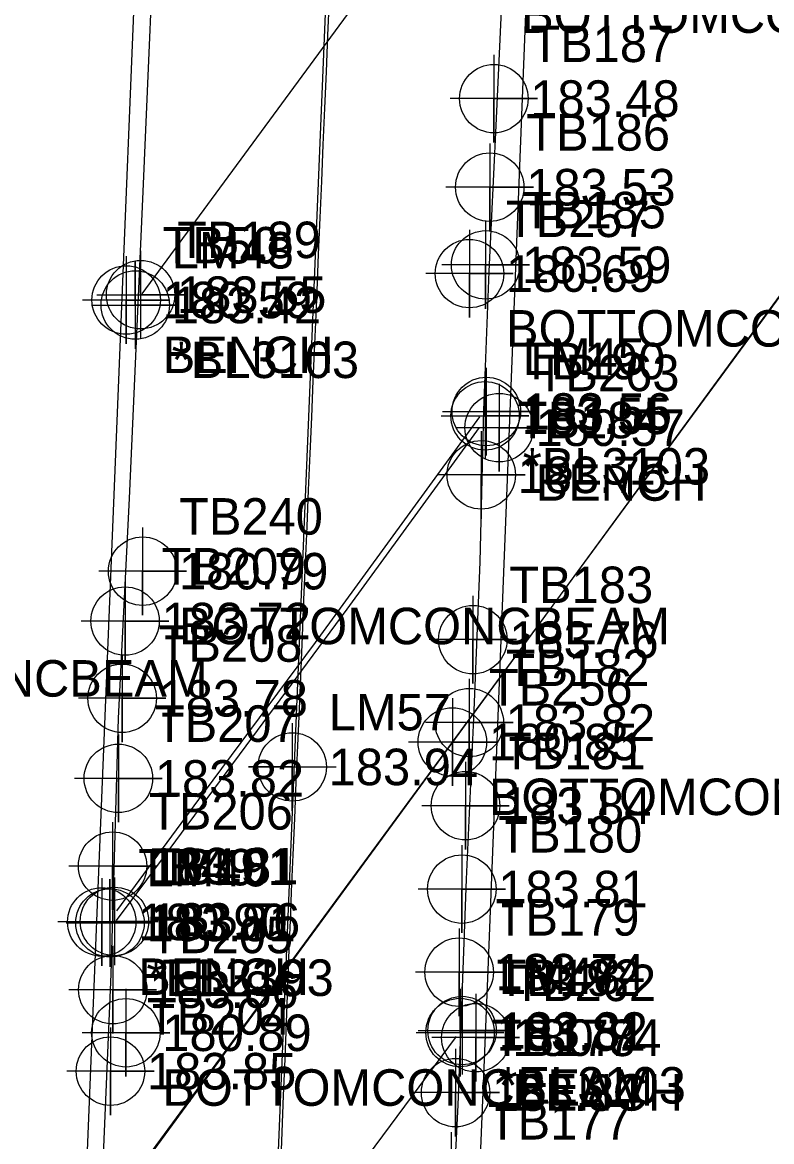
# Model space of a CAD drawing. Extents: x 2262665 to 2270527, y 505476 to 514960.
# Drawn here: x 2266313.3 to 2266364.6, y 510590.2 to 510666.8 of the extents above; entities that cross this region are included whole.
import ezdxf

# ---------------------------------------------------------------- set-up
doc = ezdxf.new("R2010")
doc.units = 0
for name, color, linetype in [('Default Symbol CELL', 7, 'Continuous'), ('Default Symbol Cogo Comment', 7, 'Continuous'), ('Default Symbol Cogo Elevation', 7, 'Continuous'), ('Default Symbol Cogo Number', 7, 'Continuous'), ('Exist Guardrail', 7, 'Continuous'), ('Exist Horizontal Alignment', 7, 'Continuous'), ('Exist Railroads Standard Gauge', 7, 'Continuous'), ('Exist Roads EOT', 7, 'Continuous'), ('Exist Roads EOT Cogo Elevation', 7, 'Continuous'), ('Exist Roads EOT Cogo Number', 7, 'Continuous'), ('Exist Roads EOT Cogo Point CELL', 7, 'Continuous'), ('Exist Structure Major Bridge Seam', 7, 'Continuous'), ('Exist Structure Major Bridge Seam Cogo Comment', 7, 'Continuous'), ('Exist Structure Major Bridge Seam Cogo Elevation', 7, 'Continuous'), ('Exist Structure Major Bridge Seam Cogo Number', 7, 'Continuous'), ('Exist Structure Major Bridge Seam Cogo Point CELL', 7, 'Continuous'), ('Exist Structure Major Deck Tunnel Box Culvert', 7, 'Continuous'), ('Exist Structure Minor Drop Inlet Cogo Elevation', 7, 'Continuous'), ('Exist Structure Minor Drop Inlet Cogo Number', 7, 'Continuous'), ('Exist Structure Minor Drop Inlet Cogo Point CELL', 7, 'Continuous')]:
    doc.layers.add(name, color=color, linetype=linetype)

msp = doc.modelspace()

# ---------------------------------------------------------------- linework, layer by layer
at = {"layer": 'Default Symbol CELL'}
for points in [[(2266343.875, 510652.617), (2266343.875, 510646.617), (2266343.875, 510649.617), (2266346.875, 510649.617), (2266340.875, 510649.617)], [(2266320.361, 510650.809), (2266320.361, 510644.809), (2266320.361, 510647.809), (2266323.361, 510647.809), (2266317.361, 510647.809)], [(2266345.909, 510642.068), (2266345.909, 510636.068), (2266345.909, 510639.068), (2266348.909, 510639.068), (2266342.909, 510639.068)], [(2266321.485, 510632.246), (2266321.485, 510626.246), (2266321.485, 510629.246), (2266324.485, 510629.246), (2266318.485, 510629.246)], [(2266342.701, 510620.552), (2266342.701, 510614.552), (2266342.701, 510617.552), (2266345.701, 510617.552), (2266339.701, 510617.552)], [(2266318.688, 510608.237), (2266318.688, 510602.237), (2266318.688, 510605.237), (2266321.688, 510605.237), (2266315.688, 510605.237)], [(2266320.34, 510600.651), (2266320.34, 510594.651), (2266320.34, 510597.651), (2266323.34, 510597.651), (2266317.34, 510597.651)], [(2266344.308, 510600.318), (2266344.308, 510594.318), (2266344.308, 510597.318), (2266347.308, 510597.318), (2266341.308, 510597.318)]]:
    msp.add_lwpolyline(points, dxfattribs=at)
for centre in [(2266343.875, 510649.617), (2266320.361, 510647.809), (2266345.909, 510639.068), (2266321.485, 510629.246), (2266342.701, 510617.552), (2266318.688, 510605.237), (2266320.34, 510597.651), (2266344.308, 510597.318)]:
    msp.add_circle(centre, 2.344, dxfattribs=at)
at = {"layer": 'Exist Guardrail'}
for points in [[(2266353.106, 510731.751), (2266351.624, 510731.138), (2266350.675, 510729.801), (2266350.418, 510728.723), (2266350.359, 510727.905), (2266350.321, 510727.053), (2266350.321, 510727.053), (2266348.476, 510686.53), (2266345.137, 510601.939), (2266341.529, 510514.133), (2266341.529, 510514.133), (2266342.739, 510511.419)], [(2266310.275, 510472.029), (2266312.516, 510474.848), (2266312.727, 510477.084), (2266316.621, 510562.638), (2266320.054, 510647.377), (2266321.754, 510688.765), (2266321.754, 510688.765), (2266321.886, 510690.484), (2266321.011, 510691.957), (2266320.201, 510692.519)]]:
    msp.add_lwpolyline(points, dxfattribs=at)
at = {"layer": 'Exist Horizontal Alignment'}
for p, q in [((2266320.496, 510340.107), (2266385.321, 511909.143)), ((2266115.369, 510308.344), (2266484.608, 510810.549))]:
    msp.add_line(p, q, dxfattribs=at)
at = {"layer": 'Exist Railroads Standard Gauge'}
msp.add_lwpolyline([(2266050.126, 510219.701), (2266084.793, 510266.487), (2266115.405, 510308.449), (2266145.346, 510349.147), (2266177.142, 510392.251), (2266205.29, 510430.675), (2266238.555, 510475.952), (2266285.007, 510539.009), (2266316.093, 510581.207), (2266370.928, 510656.017), (2266407.404, 510705.524), (2266453.51, 510768.358), (2266484.598, 510810.492), (2266484.598, 510810.492), (2266581.191, 510941.594), (2266616.47, 510989.01)], dxfattribs=at)
at = {"layer": 'Exist Roads EOT'}
msp.add_lwpolyline([(2266334.267, 510668.425), (2266334.161, 510665.928), (2266334.054, 510663.43), (2266333.948, 510660.933), (2266333.841, 510658.435), (2266333.735, 510655.938), (2266333.629, 510653.44), (2266333.522, 510650.943), (2266333.416, 510648.445), (2266333.366, 510647.285), (2266333.26, 510644.787), (2266333.154, 510642.29), (2266333.048, 510639.792), (2266332.942, 510637.294), (2266332.836, 510634.797), (2266332.73, 510632.299), (2266332.624, 510629.801), (2266332.518, 510627.304), (2266332.412, 510624.806), (2266332.199, 510619.81), (2266332.093, 510617.313), (2266331.987, 510614.815), (2266331.881, 510612.317), (2266331.775, 510609.82), (2266331.669, 510607.322), (2266331.606, 510605.841), (2266331.509, 510603.343), (2266331.412, 510600.845), (2266331.316, 510598.346), (2266331.219, 510595.848), (2266331.122, 510593.35), (2266331.025, 510590.852), (2266330.928, 510588.354)], dxfattribs=at)
at = {"layer": 'Exist Roads EOT Cogo Point CELL'}
msp.add_lwpolyline([(2266331.734, 510618.848), (2266331.734, 510612.848), (2266331.734, 510615.848), (2266328.734, 510615.848), (2266334.734, 510615.848)], dxfattribs=at)
msp.add_circle((2266331.734, 510615.848), 2.344, dxfattribs=at)
at = {"layer": 'Exist Structure Major Bridge Seam'}
for points in [[(2266321.461, 510648.224), (2266335.517, 510667.346), (2266346.37, 510682.164)], [(2266344.564, 510639.813), (2266333.295, 510624.372), (2266325.639, 510614.047), (2266319.704, 510606.008)], [(2266344.547, 510639.086), (2266335.475, 510626.651), (2266328.561, 510617.289), (2266322.827, 510609.546), (2266319.684, 510605.336)], [(2266317.994, 510563.231), (2266330.865, 510581.067), (2266342.991, 510597.386)]]:
    msp.add_lwpolyline(points, dxfattribs=at)
at = {"layer": 'Exist Structure Major Bridge Seam Cogo Point CELL'}
for points in [[(2266318.348, 510648.174), (2266324.348, 510648.174), (2266321.348, 510648.174), (2266321.348, 510651.174), (2266321.348, 510645.174)], [(2266317.985, 510647.466), (2266323.985, 510647.466), (2266320.985, 510647.466), (2266320.985, 510650.466), (2266320.985, 510644.466)], [(2266342.027, 510640.175), (2266348.027, 510640.175), (2266345.027, 510640.175), (2266345.027, 510643.175), (2266345.027, 510637.175)], [(2266341.942, 510639.881), (2266347.942, 510639.881), (2266344.942, 510639.881), (2266344.942, 510642.881), (2266344.942, 510636.881)], [(2266316.251, 510605.17), (2266322.251, 510605.17), (2266319.251, 510605.17), (2266319.251, 510608.17), (2266319.251, 510602.17)], [(2266316.553, 510605.272), (2266322.553, 510605.272), (2266319.553, 510605.272), (2266319.553, 510608.272), (2266319.553, 510602.272)], [(2266340.231, 510597.666), (2266346.231, 510597.666), (2266343.231, 510597.666), (2266343.231, 510600.666), (2266343.231, 510594.666)], [(2266340.367, 510597.802), (2266346.367, 510597.802), (2266343.367, 510597.802), (2266343.367, 510600.802), (2266343.367, 510594.802)]]:
    msp.add_lwpolyline(points, dxfattribs=at)
for centre in [(2266321.348, 510648.174), (2266320.985, 510647.466), (2266345.027, 510640.175), (2266344.942, 510639.881), (2266319.251, 510605.17), (2266319.553, 510605.272), (2266343.231, 510597.666), (2266343.367, 510597.802)]:
    msp.add_circle(centre, 2.344, dxfattribs=at)
at = {"layer": 'Exist Structure Major Deck Tunnel Box Culvert'}
for points in [[(2266323.169, 510691.254), (2266333.977, 510705.552), (2266348.664, 510725.908), (2266347.843, 510709.158), (2266347.256, 510696.096), (2266346.67, 510683.55), (2266346.252, 510672.076), (2266345.679, 510659.76), (2266345.212, 510649.756), (2266344.825, 510640.273), (2266344.583, 510629.878), (2266344.179, 510619.704), (2266343.64, 510608.154), (2266343.068, 510592.707), (2266342.216, 510575.498), (2266341.604, 510560.783), (2266341.032, 510547.019), (2266340.29, 510531.041), (2266339.3, 510510.447), (2266326.148, 510493.102)], [(2266313.738, 510476.49), (2266315.179, 510506.564), (2266315.805, 510521.526), (2266316.843, 510543.295), (2266317.691, 510561.938), (2266318.494, 510581.739), (2266319.326, 510601.662), (2266319.84, 510619.188), (2266320.579, 510634.219), (2266321.528, 510655.243), (2266322.515, 510677.939), (2266323.169, 510691.254)]]:
    msp.add_lwpolyline(points, dxfattribs=at)
at = {"layer": 'Exist Structure Minor Drop Inlet Cogo Point CELL'}
for points in [[(2266345.545, 510664.595), (2266345.545, 510658.595), (2266345.545, 510661.595), (2266348.545, 510661.595), (2266342.545, 510661.595)], [(2266345.264, 510658.531), (2266345.264, 510652.531), (2266345.264, 510655.531), (2266348.264, 510655.531), (2266342.264, 510655.531)], [(2266344.979, 510653.212), (2266344.979, 510647.212), (2266344.979, 510650.212), (2266347.979, 510650.212), (2266341.979, 510650.212)], [(2266344.68, 510638.841), (2266344.68, 510632.841), (2266344.68, 510635.841), (2266347.68, 510635.841), (2266341.68, 510635.841)], [(2266320.288, 510628.832), (2266320.288, 510622.832), (2266320.288, 510625.832), (2266323.288, 510625.832), (2266317.288, 510625.832)], [(2266344.106, 510627.561), (2266344.106, 510621.561), (2266344.106, 510624.561), (2266347.106, 510624.561), (2266341.106, 510624.561)], [(2266320.085, 510623.546), (2266320.085, 510617.546), (2266320.085, 510620.546), (2266323.085, 510620.546), (2266317.085, 510620.546)], [(2266343.863, 510621.883), (2266343.863, 510615.883), (2266343.863, 510618.883), (2266346.863, 510618.883), (2266340.863, 510618.883)], [(2266319.825, 510618.063), (2266319.825, 510612.063), (2266319.825, 510615.063), (2266322.825, 510615.063), (2266316.825, 510615.063)], [(2266343.603, 510616.194), (2266343.603, 510610.194), (2266343.603, 510613.194), (2266346.603, 510613.194), (2266340.603, 510613.194)], [(2266319.429, 510612.059), (2266319.429, 510606.059), (2266319.429, 510609.059), (2266322.429, 510609.059), (2266316.429, 510609.059)], [(2266343.353, 510610.486), (2266343.353, 510604.486), (2266343.353, 510607.486), (2266346.353, 510607.486), (2266340.353, 510607.486)], [(2266343.168, 510604.799), (2266343.168, 510598.799), (2266343.168, 510601.799), (2266346.168, 510601.799), (2266340.168, 510601.799)], [(2266319.442, 510603.598), (2266319.442, 510597.598), (2266319.442, 510600.598), (2266322.442, 510600.598), (2266316.442, 510600.598)], [(2266319.285, 510598.021), (2266319.285, 510592.021), (2266319.285, 510595.021), (2266322.285, 510595.021), (2266316.285, 510595.021)], [(2266342.922, 510596.554), (2266342.922, 510590.554), (2266342.922, 510593.554), (2266345.922, 510593.554), (2266339.922, 510593.554)], [(2266342.628, 510590.844), (2266342.628, 510584.844), (2266342.628, 510587.844), (2266345.628, 510587.844), (2266339.628, 510587.844)]]:
    msp.add_lwpolyline(points, dxfattribs=at)
for centre in [(2266345.545, 510661.595), (2266345.264, 510655.531), (2266344.979, 510650.212), (2266344.68, 510635.841), (2266320.288, 510625.832), (2266344.106, 510624.561), (2266320.085, 510620.546), (2266343.863, 510618.883), (2266319.825, 510615.063), (2266343.603, 510613.194), (2266319.429, 510609.059), (2266343.353, 510607.486), (2266343.168, 510601.799), (2266319.442, 510600.598), (2266319.285, 510595.021), (2266342.922, 510593.554)]:
    msp.add_circle(centre, 2.344, dxfattribs=at)

# ---------------------------------------------------------------- texts
at = {"layer": 'Default Symbol Cogo Comment'}
for s, p in [('BOTTOMCONCBEAM', (2266347.411, 510666.094)), ('BOTTOMCONCBEAM', (2266346.375, 510644.617)), ('BENCH', (2266322.861, 510642.809)), ('BENCH', (2266348.409, 510634.068)), ('BOTTOMCONCBEAM', (2266323.985, 510624.246)), ('BOTTOMCONCBEAM', (2266292.321, 510620.658)), ('BOTTOMCONCBEAM', (2266345.201, 510612.552)), ('BENCH', (2266321.188, 510600.237)), ('BOTTOMCONCBEAM', (2266322.84, 510592.651)), ('BENCH', (2266346.808, 510592.318))]:
    msp.add_text(s, height=2.5, dxfattribs=at).set_placement(p)
at = {"layer": 'Default Symbol Cogo Elevation'}
for s, p in [('180.69', (2266346.375, 510648.367)), ('180.59', (2266322.861, 510646.559)), ('180.57', (2266348.409, 510637.818)), ('180.79', (2266323.985, 510627.996)), ('180.85', (2266345.201, 510616.302)), ('180.90', (2266321.188, 510603.987)), ('180.89', (2266322.84, 510596.401)), ('180.74', (2266346.808, 510596.068))]:
    msp.add_text(s, height=2.5, dxfattribs=at).set_placement(p)
at = {"layer": 'Default Symbol Cogo Number'}
for s, p in [('TB257', (2266346.375, 510652.117)), ('TB50', (2266322.861, 510650.309)), ('TB263', (2266348.409, 510641.568)), ('TB240', (2266323.985, 510631.746)), ('TB256', (2266345.201, 510620.052)), ('TB49', (2266321.188, 510607.737)), ('TB239', (2266322.84, 510600.151)), ('TB262', (2266346.808, 510599.818))]:
    msp.add_text(s, height=2.5, dxfattribs=at).set_placement(p)
at = {"layer": 'Exist Roads EOT Cogo Elevation'}
msp.add_text('183.94', height=2.5, dxfattribs=at).set_placement((2266334.234, 510614.598))
at = {"layer": 'Exist Roads EOT Cogo Number'}
msp.add_text('LM57', height=2.5, dxfattribs=at).set_placement((2266334.234, 510618.348))
at = {"layer": 'Exist Structure Major Bridge Seam Cogo Comment'}
for s, p in [('*BL3103', (2266323.485, 510642.466)), ('*BL3103', (2266347.527, 510635.175)), ('*EL3103', (2266321.751, 510600.17)), ('*EL3103', (2266345.867, 510592.802))]:
    msp.add_text(s, height=2.5, dxfattribs=at).set_placement(p)
at = {"layer": 'Exist Structure Major Bridge Seam Cogo Elevation'}
for s, p in [('183.55', (2266323.848, 510646.924)), ('183.42', (2266323.485, 510646.216)), ('183.55', (2266347.442, 510638.631)), ('183.56', (2266347.527, 510638.925)), ('183.81', (2266321.751, 510603.92)), ('183.76', (2266322.053, 510604.022)), ('183.81', (2266345.731, 510596.416)), ('183.82', (2266345.867, 510596.552))]:
    msp.add_text(s, height=2.5, dxfattribs=at).set_placement(p)
at = {"layer": 'Exist Structure Major Bridge Seam Cogo Number'}
for s, p in [('TB189', (2266323.848, 510650.674)), ('LM43', (2266323.485, 510649.966)), ('TB190', (2266347.442, 510642.381)), ('LM45', (2266347.527, 510642.675)), ('TB191', (2266322.053, 510607.772)), ('LM46', (2266321.751, 510607.67)), ('TB192', (2266345.731, 510600.166)), ('LM48', (2266345.867, 510600.302))]:
    msp.add_text(s, height=2.5, dxfattribs=at).set_placement(p)
at = {"layer": 'Exist Structure Minor Drop Inlet Cogo Elevation'}
for s, p in [('183.48', (2266348.045, 510660.345)), ('183.53', (2266347.764, 510654.281)), ('183.59', (2266347.479, 510648.962)), ('183.75', (2266347.18, 510634.591)), ('183.72', (2266322.788, 510624.582)), ('183.76', (2266346.606, 510623.311)), ('183.78', (2266322.585, 510619.296)), ('183.82', (2266346.363, 510617.633)), ('183.82', (2266322.325, 510613.813)), ('183.84', (2266346.103, 510611.944)), ('183.81', (2266321.929, 510607.809)), ('183.81', (2266345.853, 510606.236)), ('183.74', (2266345.668, 510600.549)), ('183.86', (2266321.942, 510599.348)), ('183.85', (2266321.785, 510593.771)), ('183.84', (2266345.422, 510592.304))]:
    msp.add_text(s, height=2.5, dxfattribs=at).set_placement(p)
at = {"layer": 'Exist Structure Minor Drop Inlet Cogo Number'}
for s, p in [('TB187', (2266348.045, 510664.095)), ('TB186', (2266347.764, 510658.031)), ('TB185', (2266347.479, 510652.712)), ('TB184', (2266347.18, 510638.341)), ('TB209', (2266322.788, 510628.332)), ('TB183', (2266346.606, 510627.061)), ('TB208', (2266322.585, 510623.046)), ('TB182', (2266346.363, 510621.383)), ('TB207', (2266322.325, 510617.563)), ('TB181', (2266346.103, 510615.694)), ('TB206', (2266321.929, 510611.559)), ('TB180', (2266345.853, 510609.986)), ('TB179', (2266345.668, 510604.299)), ('TB205', (2266321.942, 510603.098)), ('TB204', (2266321.785, 510597.521)), ('TB178', (2266345.422, 510596.054)), ('TB177', (2266345.128, 510590.344))]:
    msp.add_text(s, height=2.5, dxfattribs=at).set_placement(p)

doc.saveas('drawing.dxf')
